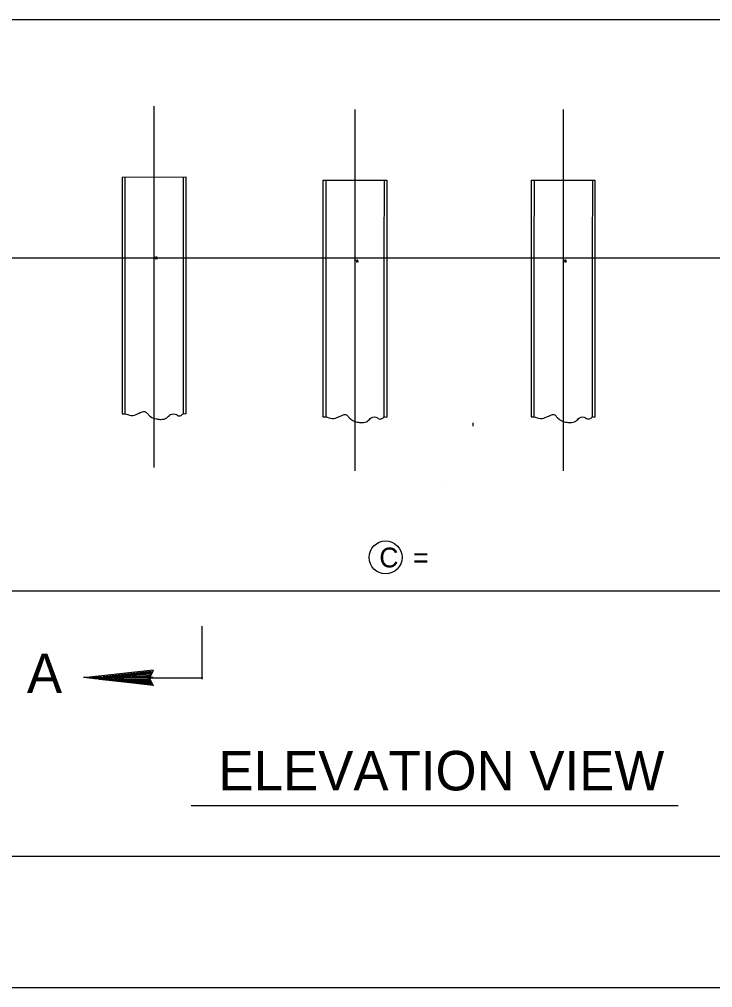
# Model space of a CAD drawing. Extents: x 1.6 to 6.29, y 2.8 to 7.08.
# Drawn here: x 2.935 to 3.374, y 4.675 to 5.288 of the extents above; entities that cross this region are included whole.
import ezdxf

# ---------------------------------------------------------------- set-up
doc = ezdxf.new("R2010")
doc.units = 0
doc.layers.add('Level 1', color=7, linetype='Continuous')
doc.layers.add('Level 5', color=7, linetype='Continuous')

msp = doc.modelspace()

# ---------------------------------------------------------------- linework, layer by layer
at = {"layer": 'Level 1'}
for p, q in [((2.91025, 5.28792), (3.2215, 5.28792)), ((2.91025, 5.28792), (3.2215, 5.28792)), ((3.2215, 5.28792), (3.51525, 5.28792)), ((3.2215, 5.28792), (3.51525, 5.28792)), ((3.22175, 5.13667), (2.80942, 5.13667)), ((3.22175, 5.13667), (2.80942, 5.13667)), ((3.61608, 5.13667), (3.22175, 5.13667)), ((3.61608, 5.13667), (3.22175, 5.13667)), ((3.22192, 5.03233), (3.22192, 5.03017)), ((3.22192, 5.03233), (3.22192, 5.03017)), ((3.20258, 4.99308), (3.20267, 4.99308)), ((3.20258, 4.99308), (3.20267, 4.99308)), ((2.81058, 4.92592), (3.20292, 4.92592)), ((3.19942, 4.92592), (3.61358, 4.92592)), ((3.05033, 4.90367), (3.05033, 4.87008)), ((2.97525, 4.87108), (3.01942, 4.876)), ((2.97525, 4.87108), (3.01942, 4.876)), ((3.01933, 4.87558), (3.017, 4.87058)), ((3.01933, 4.87558), (3.017, 4.87058)), ((3.01942, 4.87117), (2.97525, 4.87117)), ((3.01942, 4.87117), (2.97525, 4.87117)), ((3.0195, 4.86608), (2.97533, 4.871)), ((3.0195, 4.86608), (2.97533, 4.871)), ((2.98658, 4.87142), (2.98117, 4.87092)), ((2.98658, 4.87142), (2.98117, 4.87092)), ((2.98117, 4.87092), (3.01633, 4.87108)), ((2.98117, 4.87092), (3.01633, 4.87108)), ((2.9825, 4.87033), (2.98658, 4.87142)), ((2.9825, 4.87033), (2.98658, 4.87142)), ((3.00217, 4.8695), (2.9825, 4.87033)), ((3.00217, 4.8695), (2.9825, 4.87033)), ((3.01842, 4.86667), (2.9855, 4.87017)), ((3.01842, 4.86667), (2.9855, 4.87017)), ((3.01842, 4.8665), (2.9855, 4.87008)), ((3.01842, 4.8665), (2.9855, 4.87008)), ((3.01833, 4.86633), (2.9855, 4.86992)), ((3.01833, 4.86633), (2.9855, 4.86992)), ((3.0185, 4.86725), (2.98567, 4.87083)), ((3.0185, 4.86725), (2.98567, 4.87083)), ((3.01842, 4.86683), (2.98567, 4.8705)), ((3.01842, 4.86683), (2.98567, 4.8705)), ((3.01833, 4.87483), (2.98767, 4.8715)), ((3.01833, 4.87483), (2.98767, 4.8715)), ((3.01842, 4.87442), (2.98775, 4.87108)), ((3.01842, 4.87442), (2.98775, 4.87108)), ((3.0185, 4.87392), (2.98792, 4.87058)), ((3.0185, 4.87392), (2.98792, 4.87058)), ((3.01858, 4.87342), (2.98792, 4.87008)), ((3.01858, 4.87342), (2.98792, 4.87008)), ((2.99442, 4.87017), (3.01708, 4.87267)), ((2.99442, 4.87017), (3.01708, 4.87267)), ((3.01692, 4.87175), (2.99442, 4.87017)), ((3.01692, 4.87175), (2.99442, 4.87017)), ((2.99667, 4.86983), (2.99675, 4.87033)), ((2.99667, 4.86983), (2.99675, 4.87033)), ((3.01633, 4.87008), (2.99667, 4.86983)), ((3.01633, 4.87008), (2.99667, 4.86983)), ((2.99675, 4.87033), (3.00058, 4.87008)), ((2.99675, 4.87033), (3.00058, 4.87008)), ((3.00058, 4.87008), (3.01633, 4.86983)), ((3.00058, 4.87008), (3.01633, 4.86983)), ((3.01725, 4.86833), (3.00217, 4.8695)), ((3.01725, 4.86833), (3.00217, 4.8695)), ((3.01633, 4.86983), (3.00367, 4.86942)), ((3.01633, 4.86983), (3.00367, 4.86942)), ((3.00367, 4.86942), (3.01692, 4.86917)), ((3.00367, 4.86942), (3.01692, 4.86917)), ((3.01633, 4.87108), (3.00608, 4.87175)), ((3.00608, 4.87175), (3.01692, 4.87175)), ((3.01633, 4.87108), (3.00608, 4.87175)), ((3.00608, 4.87175), (3.01692, 4.87175)), ((3.01625, 4.8695), (3.01508, 4.869)), ((3.01625, 4.8695), (3.01508, 4.869)), ((3.01583, 4.86758), (3.0165, 4.87075)), ((3.01583, 4.86758), (3.0165, 4.87075)), ((3.01708, 4.87267), (3.01625, 4.87017)), ((3.01708, 4.87267), (3.01625, 4.87017)), ((3.01625, 4.87017), (3.01808, 4.86708)), ((3.01625, 4.87017), (3.01808, 4.86708)), ((3.01708, 4.86775), (3.01625, 4.8695)), ((3.01708, 4.86775), (3.01625, 4.8695)), ((3.0165, 4.87075), (3.01742, 4.87267)), ((3.0165, 4.87075), (3.01742, 4.87267)), ((3.017, 4.87058), (3.01933, 4.86575)), ((3.017, 4.87058), (3.01933, 4.86575)), ((3.05092, 4.87075), (3.01717, 4.87075)), ((3.01742, 4.87267), (3.01833, 4.87483)), ((3.01742, 4.87267), (3.01833, 4.87483)), ((3.01692, 4.86917), (3.00758, 4.86883)), ((3.01692, 4.86917), (3.00758, 4.86883)), ((3.00758, 4.86883), (3.01725, 4.86833)), ((3.00758, 4.86883), (3.01725, 4.86833)), ((3.01508, 4.869), (3.01583, 4.86758)), ((3.01508, 4.869), (3.01583, 4.86758)), ((3.01808, 4.86708), (3.01708, 4.86775)), ((3.01808, 4.86708), (3.01708, 4.86775)), ((3.35192, 4.78983), (3.04358, 4.78983)), ((2.55808, 4.758), (6.18475, 4.758)), ((2.55808, 4.758), (5.46475, 4.758)), ((2.39142, 4.67467), (6.26142, 4.67467))]:
    msp.add_line(p, q, dxfattribs=at)
msp.add_circle((3.16662, 4.94715), 0.01042, dxfattribs=at)
at = {"layer": 'Level 5'}
for p, q in [((3.01983, 5.23292), (3.01983, 5.14)), ((3.14708, 5.23092), (3.14708, 5.14)), ((3.279, 5.23092), (3.279, 5.14)), ((2.99967, 5.188), (3.04008, 5.18808)), ((2.99967, 5.188), (2.99967, 5.14)), ((3.0015, 5.18808), (3.00142, 5.14)), ((3.03842, 5.18808), (3.03833, 5.14)), ((3.04008, 5.18808), (3.04008, 5.14)), ((3.12692, 5.186), (3.16733, 5.18608)), ((3.12692, 5.186), (3.12692, 5.14)), ((3.12875, 5.18608), (3.12867, 5.14)), ((3.16567, 5.18608), (3.16558, 5.14)), ((3.16733, 5.18608), (3.16733, 5.14)), ((3.25883, 5.186), (3.29925, 5.18608)), ((3.25883, 5.186), (3.25883, 5.14)), ((3.26067, 5.18608), (3.26058, 5.14)), ((3.29758, 5.18608), (3.2975, 5.14)), ((3.29925, 5.18608), (3.29925, 5.14)), ((2.99967, 5.14), (2.99967, 5.03808)), ((3.00142, 5.14), (3.00142, 5.03808)), ((3.01983, 5.14), (3.01992, 5.004)), ((3.03833, 5.14), (3.03833, 5.03808)), ((3.04008, 5.14), (3.04008, 5.038)), ((3.12692, 5.14), (3.12692, 5.03608)), ((3.12867, 5.14), (3.12867, 5.03608)), ((3.14708, 5.14), (3.14717, 5.002)), ((3.16558, 5.14), (3.16558, 5.03608)), ((3.16733, 5.14), (3.16733, 5.036)), ((3.25883, 5.14), (3.25883, 5.03608)), ((3.26058, 5.14), (3.26058, 5.03608)), ((3.279, 5.14), (3.27908, 5.002)), ((3.2975, 5.14), (3.2975, 5.03608)), ((3.29925, 5.14), (3.29925, 5.036))]:
    msp.add_line(p, q, dxfattribs=at)
for points in [[(2.99967, 5.03808), (3.00142, 5.03808), (3.0055, 5.03708), (3.00958, 5.03808), (3.01175, 5.03908), (3.01458, 5.03942), (3.01508, 5.039), (3.0165, 5.03742), (3.01775, 5.03633), (3.0215, 5.03483), (3.02433, 5.03458), (3.028, 5.0355), (3.03033, 5.03758), (3.03417, 5.03758), (3.03533, 5.03683), (3.03758, 5.03742), (3.03833, 5.03808), (3.04008, 5.038)], [(3.12692, 5.03608), (3.12867, 5.03608), (3.13275, 5.03508), (3.13683, 5.03608), (3.139, 5.03708), (3.14183, 5.03742), (3.14233, 5.037), (3.14375, 5.03542), (3.145, 5.03433), (3.14875, 5.03283), (3.15158, 5.03258), (3.15525, 5.0335), (3.15758, 5.03558), (3.16142, 5.03558), (3.16258, 5.03483), (3.16483, 5.03542), (3.16558, 5.03608), (3.16733, 5.036)], [(3.25883, 5.03608), (3.26058, 5.03608), (3.26467, 5.03508), (3.26875, 5.03608), (3.27092, 5.03708), (3.27375, 5.03742), (3.27425, 5.037), (3.27567, 5.03542), (3.27692, 5.03433), (3.28067, 5.03283), (3.2835, 5.03258), (3.28717, 5.0335), (3.2895, 5.03558), (3.29333, 5.03558), (3.2945, 5.03483), (3.29675, 5.03542), (3.2975, 5.03608), (3.29925, 5.036)]]:
    msp.add_spline(points, degree=3, dxfattribs=at)

# ---------------------------------------------------------------- texts
at = {"layer": 'Level 1'}
for s, p in [('A', (2.93942, 4.86125)), ('ELEVATION VIEW', (3.06075, 4.79958))]:
    msp.add_text(s, height=0.025, dxfattribs=at).set_placement(p)
at = {"layer": 'Level 5'}
for p in [(3.01933, 5.13533), (3.14658, 5.13333), (3.2785, 5.13333)]:
    msp.add_text('.', height=0.0125, rotation=14.0362, dxfattribs=at).set_placement(p)
msp.add_text('C  =      ', height=0.0125, dxfattribs=at).set_placement((3.16267, 4.94083))

doc.saveas('drawing.dxf')
